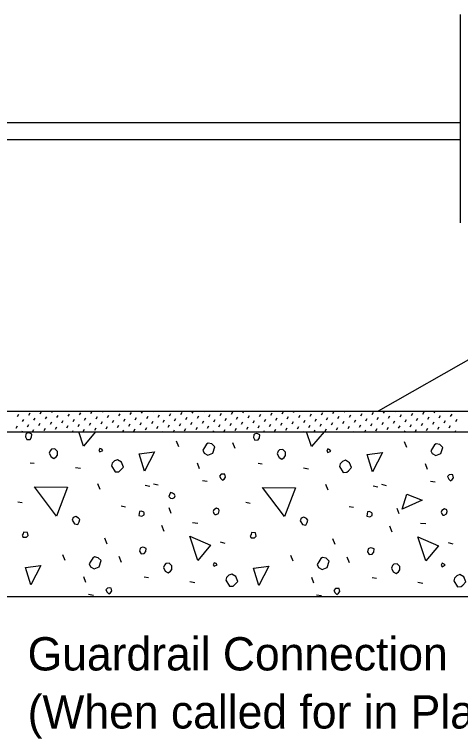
# Model space of a CAD drawing. Extents: x 130649.2 to 130733.9, y 88659.3 to 88705.5.
# Drawn here: x 130683.854 to 130686.559, y 88685.896 to 88690.285 of the extents above; entities that cross this region are included whole.
import ezdxf

# ---------------------------------------------------------------- set-up
doc = ezdxf.new("R2010")
doc.units = 0
for name, color, linetype in [('AdhocPoint_dp', 7, 'Continuous'), ('PlotBorder_dp', 7, 'Continuous'), ('TextMisc', 7, 'Continuous')]:
    doc.layers.add(name, color=color, linetype=linetype)

msp = doc.modelspace()

# ---------------------------------------------------------------- linework, layer by layer
at = {"layer": 'AdhocPoint_dp'}
for p, q in [((130673.2282, 88689.6313), (130686.5589, 88689.6313)), ((130689.0589, 88689.5896), (130686.0591, 88687.8812)), ((130673.2282, 88689.5271), (130686.5589, 88689.5271)), ((130673.2282, 88687.8812), (130689.0593, 88687.8812)), ((130673.2282, 88687.7562), (130689.0593, 88687.7562)), ((130673.2282, 88686.7562), (130689.0593, 88686.7562))]:
    msp.add_line(p, q, dxfattribs=at)
at = {"layer": 'TextMisc'}
for p, q in [((130686.559, 88689.0229), (130686.5589, 88690.2852)), ((130683.942, 88687.8556), (130683.9501, 88687.8696)), ((130684.0112, 88687.8637), (130684.0193, 88687.8777)), ((130684.0804, 88687.8718), (130684.0858, 88687.8812)), ((130684.1495, 88687.8799), (130684.1503, 88687.8812)), ((130684.2492, 88687.8575), (130684.2573, 88687.8715)), ((130684.3184, 88687.8656), (130684.3265, 88687.8796)), ((130684.3876, 88687.8737), (130684.3919, 88687.8812)), ((130684.4873, 88687.8513), (130684.4954, 88687.8653)), ((130684.5564, 88687.8594), (130684.5645, 88687.8734)), ((130684.6256, 88687.8675), (130684.6335, 88687.8812)), ((130684.6947, 88687.8756), (130684.698, 88687.8812)), ((130684.7944, 88687.8532), (130684.8025, 88687.8672)), ((130684.8636, 88687.8613), (130684.8717, 88687.8753)), ((130684.9328, 88687.8694), (130684.9396, 88687.8812)), ((130685.0019, 88687.8775), (130685.0041, 88687.8812)), ((130685.1016, 88687.8551), (130685.1097, 88687.869)), ((130685.1708, 88687.8632), (130685.1789, 88687.8771)), ((130685.24, 88687.8713), (130685.2457, 88687.8812)), ((130685.3091, 88687.8794), (130685.3102, 88687.8812)), ((130685.4088, 88687.8569), (130685.4169, 88687.8709)), ((130685.478, 88687.865), (130685.4861, 88687.879)), ((130685.5471, 88687.8731), (130685.5518, 88687.8812)), ((130685.6468, 88687.8507), (130685.6549, 88687.8647)), ((130685.716, 88687.8588), (130685.7241, 88687.8728)), ((130685.7852, 88687.8669), (130685.7933, 88687.8809)), ((130685.8543, 88687.875), (130685.8579, 88687.8812)), ((130685.954, 88687.8526), (130685.9621, 88687.8666)), ((130686.0232, 88687.8607), (130686.0313, 88687.8747)), ((130686.0923, 88687.8688), (130686.0995, 88687.8812)), ((130686.1615, 88687.8769), (130686.164, 88687.8812)), ((130686.2612, 88687.8545), (130686.2693, 88687.8685)), ((130686.3304, 88687.8626), (130686.3385, 88687.8766)), ((130686.3995, 88687.8707), (130686.4056, 88687.8812)), ((130686.4687, 88687.8788), (130686.4701, 88687.8812)), ((130683.8729, 88687.8475), (130683.881, 88687.8615)), ((130683.9034, 88687.817), (130683.9115, 88687.831)), ((130683.9726, 88687.8251), (130683.9807, 88687.8391)), ((130684.0417, 88687.8332), (130684.0498, 88687.8472)), ((130684.1109, 88687.8413), (130684.119, 88687.8553)), ((130684.1414, 88687.8108), (130684.1495, 88687.8248)), ((130684.1801, 88687.8494), (130684.1882, 88687.8634)), ((130684.2106, 88687.8189), (130684.2187, 88687.8329)), ((130684.2798, 88687.827), (130684.2879, 88687.841)), ((130684.3489, 88687.8351), (130684.357, 88687.8491)), ((130684.4181, 88687.8432), (130684.4262, 88687.8572)), ((130684.4486, 88687.8127), (130684.4567, 88687.8267)), ((130684.5178, 88687.8208), (130684.5259, 88687.8348)), ((130684.5869, 88687.8289), (130684.5951, 88687.8429)), ((130684.6561, 88687.837), (130684.6642, 88687.851)), ((130684.6866, 88687.8064), (130684.6947, 88687.8204)), ((130684.7253, 88687.8451), (130684.7334, 88687.8591)), ((130684.7558, 88687.8145), (130684.7639, 88687.8285)), ((130684.825, 88687.8226), (130684.8331, 88687.8366)), ((130684.8941, 88687.8307), (130684.9022, 88687.8447)), ((130684.9633, 88687.8388), (130684.9714, 88687.8528)), ((130684.9938, 88687.8083), (130685.0019, 88687.8223)), ((130685.0325, 88687.8469), (130685.0406, 88687.8609)), ((130685.063, 88687.8164), (130685.0711, 88687.8304)), ((130685.1322, 88687.8245), (130685.1403, 88687.8385)), ((130685.2013, 88687.8326), (130685.2094, 88687.8466)), ((130685.2705, 88687.8407), (130685.2786, 88687.8547)), ((130685.301, 88687.8102), (130685.3091, 88687.8242)), ((130685.3396, 88687.8488), (130685.3478, 88687.8628)), ((130685.3702, 88687.8183), (130685.3783, 88687.8323)), ((130685.4393, 88687.8264), (130685.4474, 88687.8404)), ((130685.5085, 88687.8345), (130685.5166, 88687.8485)), ((130685.5777, 88687.8426), (130685.5858, 88687.8566)), ((130685.6082, 88687.8121), (130685.6163, 88687.8261)), ((130685.6774, 88687.8202), (130685.6855, 88687.8342)), ((130685.7465, 88687.8283), (130685.7546, 88687.8423)), ((130685.8157, 88687.8364), (130685.8238, 88687.8504)), ((130685.8849, 88687.8445), (130685.893, 88687.8585)), ((130685.9154, 88687.814), (130685.9235, 88687.8279)), ((130685.9846, 88687.8221), (130685.9927, 88687.836)), ((130686.0537, 88687.8302), (130686.0618, 88687.8442)), ((130686.1229, 88687.8383), (130686.131, 88687.8523)), ((130686.1534, 88687.8077), (130686.1615, 88687.8217)), ((130686.192, 88687.8464), (130686.2001, 88687.8604)), ((130686.2226, 88687.8158), (130686.2307, 88687.8298)), ((130686.2917, 88687.8239), (130686.2998, 88687.8379)), ((130686.3609, 88687.832), (130686.369, 88687.846)), ((130686.4301, 88687.8401), (130686.4382, 88687.8541)), ((130686.4606, 88687.8096), (130686.4687, 88687.8236)), ((130686.4992, 88687.8482), (130686.5073, 88687.8622)), ((130686.5298, 88687.8177), (130686.5379, 88687.8317)), ((130683.8648, 88687.7784), (130683.8729, 88687.7924)), ((130683.9339, 88687.7865), (130683.942, 88687.8005)), ((130684.0031, 88687.7946), (130684.0112, 88687.8086)), ((130684.0336, 88687.764), (130684.0417, 88687.778)), ((130684.0723, 88687.8027), (130684.0804, 88687.8167)), ((130684.1028, 88687.7722), (130684.1109, 88687.7861)), ((130684.172, 88687.7803), (130684.1801, 88687.7942)), ((130684.2411, 88687.7884), (130684.2492, 88687.8024)), ((130684.3103, 88687.7965), (130684.3184, 88687.8105)), ((130684.3408, 88687.7659), (130684.3489, 88687.7799)), ((130684.3795, 88687.8046), (130684.3876, 88687.8186)), ((130684.41, 88687.774), (130684.4181, 88687.788)), ((130684.4792, 88687.7821), (130684.4873, 88687.7961)), ((130684.5483, 88687.7902), (130684.5564, 88687.8042)), ((130684.6175, 88687.7983), (130684.6256, 88687.8123)), ((130684.648, 88687.7678), (130684.6561, 88687.7818)), ((130684.7172, 88687.7759), (130684.7253, 88687.7899)), ((130684.7863, 88687.784), (130684.7944, 88687.798)), ((130684.8555, 88687.7921), (130684.8636, 88687.8061)), ((130684.9247, 88687.8002), (130684.9328, 88687.8142)), ((130684.9552, 88687.7697), (130684.9633, 88687.7837)), ((130685.0244, 88687.7778), (130685.0325, 88687.7918)), ((130685.0935, 88687.7859), (130685.1016, 88687.7999)), ((130685.1627, 88687.794), (130685.1708, 88687.808)), ((130685.1932, 88687.7635), (130685.2013, 88687.7775)), ((130685.2319, 88687.8021), (130685.24, 88687.8161)), ((130685.2624, 88687.7716), (130685.2705, 88687.7856)), ((130685.3315, 88687.7797), (130685.3396, 88687.7937)), ((130685.4007, 88687.7878), (130685.4088, 88687.8018)), ((130685.4699, 88687.7959), (130685.478, 88687.8099)), ((130685.5004, 88687.7653), (130685.5085, 88687.7793)), ((130685.539, 88687.804), (130685.5471, 88687.818)), ((130685.5696, 88687.7734), (130685.5777, 88687.7874)), ((130685.6387, 88687.7815), (130685.6468, 88687.7955)), ((130685.7079, 88687.7896), (130685.716, 88687.8036)), ((130685.7771, 88687.7977), (130685.7852, 88687.8117)), ((130685.8076, 88687.7672), (130685.8157, 88687.7812)), ((130685.8462, 88687.8058), (130685.8543, 88687.8198)), ((130685.8768, 88687.7753), (130685.8849, 88687.7893)), ((130685.9459, 88687.7834), (130685.954, 88687.7974)), ((130686.0151, 88687.7915), (130686.0232, 88687.8055)), ((130686.0842, 88687.7996), (130686.0923, 88687.8136)), ((130686.1148, 88687.7691), (130686.1229, 88687.7831)), ((130686.1839, 88687.7772), (130686.192, 88687.7912)), ((130686.2531, 88687.7853), (130686.2612, 88687.7993)), ((130686.3223, 88687.7934), (130686.3304, 88687.8074)), ((130686.3528, 88687.7629), (130686.3609, 88687.7769)), ((130686.3914, 88687.8015), (130686.3995, 88687.8155)), ((130686.422, 88687.771), (130686.4301, 88687.785)), ((130686.4911, 88687.7791), (130686.4992, 88687.7931)), ((130683.9002, 88687.7562), (130683.9034, 88687.7618)), ((130683.9646, 88687.7562), (130683.9726, 88687.7699)), ((130684.2063, 88687.7562), (130684.2106, 88687.7637)), ((130684.2717, 88687.7578), (130684.2798, 88687.7718)), ((130684.4479, 88687.7562), (130684.4486, 88687.7575)), ((130684.5124, 88687.7562), (130684.5178, 88687.7656)), ((130684.5788, 88687.7597), (130684.5869, 88687.7737)), ((130684.754, 88687.7562), (130684.7558, 88687.7594)), ((130684.8185, 88687.7562), (130684.825, 88687.7675)), ((130684.886, 88687.7616), (130684.8941, 88687.7756)), ((130685.0601, 88687.7562), (130685.063, 88687.7612)), ((130685.1246, 88687.7562), (130685.1322, 88687.7694)), ((130685.3662, 88687.7562), (130685.3702, 88687.7631)), ((130685.4312, 88687.7572), (130685.4393, 88687.7712)), ((130685.6078, 88687.7562), (130685.6082, 88687.7569)), ((130685.6723, 88687.7562), (130685.6774, 88687.765)), ((130685.7384, 88687.7591), (130685.7465, 88687.7731)), ((130685.9139, 88687.7562), (130685.9154, 88687.7588)), ((130685.9784, 88687.7562), (130685.9846, 88687.7669)), ((130686.0456, 88687.761), (130686.0537, 88687.775)), ((130686.22, 88687.7562), (130686.2226, 88687.7607)), ((130686.2845, 88687.7562), (130686.2917, 88687.7688)), ((130686.5261, 88687.7562), (130686.5298, 88687.7625)), ((130684.8504, 88687.6639), (130684.8362, 88687.6992)), ((130685.1933, 88687.6533), (130685.1792, 88687.6886)), ((130686.2328, 88687.6603), (130686.2186, 88687.6957)), ((130683.9488, 88687.5684), (130683.9736, 88687.5649)), ((130684.9759, 88687.5313), (130684.9635, 88687.5649)), ((130685.3312, 88687.5649), (130685.356, 88687.5614)), ((130686.3583, 88687.5278), (130686.3459, 88687.5614)), ((130684.2246, 88687.5401), (130684.2546, 88687.5348)), ((130685.607, 88687.5366), (130685.637, 88687.5313)), ((130684.3731, 88687.4058), (130684.3607, 88687.4394)), ((130684.6471, 88687.4323), (130684.6754, 88687.4252)), ((130684.6983, 88687.4411), (130684.7266, 88687.4341)), ((130684.9936, 88687.4606), (130685.0236, 88687.4553)), ((130685.7555, 88687.4023), (130685.7431, 88687.4358)), ((130686.0295, 88687.4288), (130686.0578, 88687.4217)), ((130686.0807, 88687.4376), (130686.109, 88687.4305)), ((130686.376, 88687.4571), (130686.406, 88687.4518)), ((130683.8746, 88687.3315), (130683.9011, 88687.3262)), ((130684.5004, 88687.3068), (130684.5269, 88687.3015)), ((130684.8044, 88687.2608), (130684.792, 88687.2944)), ((130685.257, 88687.328), (130685.2835, 88687.3227)), ((130685.8828, 88687.3033), (130685.9093, 88687.298)), ((130686.1868, 88687.2573), (130686.1744, 88687.2909)), ((130684.9335, 88687.206), (130684.9653, 88687.2025)), ((130684.762, 88687.1512), (130684.7478, 88687.1866)), ((130686.1444, 88687.1477), (130686.1302, 88687.1831)), ((130686.3159, 88687.2025), (130686.3477, 88687.199)), ((130684.4173, 88687.0752), (130684.4031, 88687.1106)), ((130685.1014, 88687.0876), (130685.1297, 88687.0805)), ((130685.7997, 88687.0717), (130685.7855, 88687.107)), ((130686.4838, 88687.0841), (130686.5121, 88687.077)), ((130684.1609, 88686.9745), (130684.1468, 88687.0098)), ((130684.5039, 88686.9638), (130684.4898, 88686.9992)), ((130685.5433, 88686.9709), (130685.5292, 88687.0063)), ((130685.8863, 88686.9603), (130685.8721, 88686.9957)), ((130684.2865, 88686.8419), (130684.2741, 88686.8755)), ((130684.6418, 88686.8755), (130684.6665, 88686.8719)), ((130685.6689, 88686.8383), (130685.6565, 88686.8719)), ((130686.0242, 88686.8719), (130686.0489, 88686.8684)), ((130684.9176, 88686.8472), (130684.9476, 88686.8419)), ((130686.2999, 88686.8436), (130686.33, 88686.8383)), ((130684.3041, 88686.7712), (130684.3342, 88686.7659)), ((130685.6865, 88686.7676), (130685.7166, 88686.7623))]:
    msp.add_line(p, q, dxfattribs=at)
for points in [[(130683.9205, 88687.724), (130683.9294, 88687.7081), (130683.9488, 88687.7098), (130683.9577, 88687.7222), (130683.9594, 88687.7417), (130683.947, 88687.747), (130683.9382, 88687.7487), (130683.9276, 88687.7452), (130683.9241, 88687.7417), (130683.9205, 88687.724)], [(130684.2723, 88687.6692), (130684.244, 88687.7562)], [(130684.346, 88687.7562), (130684.2723, 88687.6692)], [(130685.3029, 88687.7205), (130685.3118, 88687.7045), (130685.3312, 88687.7063), (130685.34, 88687.7187), (130685.3418, 88687.7381), (130685.3294, 88687.7434), (130685.3206, 88687.7452), (130685.31, 88687.7417), (130685.3065, 88687.7381), (130685.3029, 88687.7205)], [(130685.6547, 88687.6657), (130685.6253, 88687.7562)], [(130685.7313, 88687.7562), (130685.6547, 88687.6657)], [(130684.0655, 88687.625), (130684.0761, 88687.6038), (130684.0938, 88687.5932), (130684.1079, 88687.6038), (130684.115, 88687.6144), (130684.115, 88687.6356), (130684.0991, 88687.6515), (130684.0796, 88687.6497), (130684.0708, 88687.6409), (130684.0655, 88687.625)], [(130684.3713, 88687.6338), (130684.3908, 88687.6427), (130684.3837, 88687.6497), (130684.3713, 88687.655), (130684.366, 88687.6427), (130684.3713, 88687.6338)], [(130685.0042, 88687.6268), (130685.0272, 88687.6144), (130685.0572, 88687.6268), (130685.0696, 88687.6639), (130685.0519, 88687.6816), (130685.0289, 88687.6869), (130685.0183, 88687.6798), (130685.0059, 88687.6603), (130684.9971, 88687.6444), (130685.0042, 88687.6268)], [(130685.4479, 88687.6215), (130685.4585, 88687.6002), (130685.4762, 88687.5896), (130685.4903, 88687.6002), (130685.4974, 88687.6109), (130685.4974, 88687.6321), (130685.4815, 88687.648), (130685.462, 88687.6462), (130685.4532, 88687.6374), (130685.4479, 88687.6215)], [(130685.7537, 88687.6303), (130685.7732, 88687.6391), (130685.7661, 88687.6462), (130685.7537, 88687.6515), (130685.7484, 88687.6391), (130685.7537, 88687.6303)], [(130686.3866, 88687.6232), (130686.4095, 88687.6109), (130686.4396, 88687.6232), (130686.452, 88687.6603), (130686.4343, 88687.678), (130686.4113, 88687.6833), (130686.4007, 88687.6763), (130686.3883, 88687.6568), (130686.3795, 88687.6409), (130686.3866, 88687.6232)], [(130684.6435, 88687.5172), (130684.61, 88687.6215), (130684.7037, 88687.6338), (130684.6435, 88687.5172)], [(130686.0259, 88687.5136), (130685.9924, 88687.6179), (130686.086, 88687.6303), (130686.0259, 88687.5136)], [(130684.442, 88687.549), (130684.465, 88687.5119), (130684.488, 88687.5136), (130684.4968, 88687.5225), (130684.5163, 88687.5419), (130684.5039, 88687.572), (130684.4791, 88687.5861), (130684.4615, 88687.579), (130684.4473, 88687.5649), (130684.442, 88687.549)], [(130685.8244, 88687.5454), (130685.8474, 88687.5083), (130685.8704, 88687.5101), (130685.8792, 88687.5189), (130685.8987, 88687.5384), (130685.8863, 88687.5684), (130685.8615, 88687.5826), (130685.8439, 88687.5755), (130685.8297, 88687.5614), (130685.8244, 88687.5454)], [(130685.1049, 88687.473), (130685.1155, 88687.4624), (130685.1261, 88687.4694), (130685.1332, 88687.48), (130685.1297, 88687.4977), (130685.1208, 88687.4995), (130685.1085, 88687.4977), (130685.0979, 88687.4871), (130685.1049, 88687.473)], [(130686.4873, 88687.4694), (130686.4979, 88687.4588), (130686.5085, 88687.4659), (130686.5156, 88687.4765), (130686.5121, 88687.4942), (130686.5032, 88687.4959), (130686.4909, 88687.4942), (130686.4803, 88687.4836), (130686.4873, 88687.4694)], [(130684.1097, 88687.2449), (130683.9753, 88687.4217), (130684.1751, 88687.4199), (130684.1097, 88687.2449)], [(130684.8009, 88687.3528), (130684.8133, 88687.351), (130684.8256, 88687.3563), (130684.8292, 88687.3669), (130684.8239, 88687.3757), (130684.8133, 88687.3828), (130684.8009, 88687.3881), (130684.7938, 88687.374), (130684.7903, 88687.3634), (130684.8009, 88687.3528)], [(130685.4921, 88687.2414), (130685.3577, 88687.4182), (130685.5575, 88687.4164), (130685.4921, 88687.2414)], [(130686.2045, 88687.2856), (130686.2328, 88687.3775), (130686.3265, 88687.3404), (130686.2045, 88687.2856)], [(130684.6082, 88687.2485), (130684.6276, 88687.2432), (130684.64, 88687.252), (130684.6418, 88687.2644), (130684.6382, 88687.2679), (130684.6241, 88687.275), (130684.6117, 88687.2732), (130684.61, 88687.2608), (130684.6082, 88687.2485)], [(130685.0696, 88687.2538), (130685.0767, 88687.2538), (130685.0908, 88687.2608), (130685.0961, 88687.2767), (130685.0943, 88687.2856), (130685.0802, 88687.2927), (130685.0625, 88687.282), (130685.059, 88687.2714), (130685.0625, 88687.2608), (130685.0696, 88687.2538)], [(130685.9906, 88687.2449), (130686.01, 88687.2396), (130686.0224, 88687.2485), (130686.0242, 88687.2608), (130686.0206, 88687.2644), (130686.0065, 88687.2714), (130685.9941, 88687.2697), (130685.9924, 88687.2573), (130685.9906, 88687.2449)], [(130686.452, 88687.2502), (130686.459, 88687.2502), (130686.4732, 88687.2573), (130686.4785, 88687.2732), (130686.4767, 88687.282), (130686.4626, 88687.2891), (130686.4449, 88687.2785), (130686.4414, 88687.2679), (130686.4449, 88687.2573), (130686.452, 88687.2502)], [(130684.2087, 88687.2131), (130684.2175, 88687.1972), (130684.2387, 88687.1937), (130684.2476, 88687.2096), (130684.2511, 88687.2237), (130684.2423, 88687.2325), (130684.2264, 88687.2414), (130684.2104, 88687.2361), (130684.2051, 88687.2202), (130684.2087, 88687.2131)], [(130685.5911, 88687.2096), (130685.5999, 88687.1937), (130685.6211, 88687.1901), (130685.63, 88687.206), (130685.6335, 88687.2202), (130685.6247, 88687.229), (130685.6087, 88687.2379), (130685.5928, 88687.2325), (130685.5875, 88687.2166), (130685.5911, 88687.2096)], [(130683.9064, 88687.1159), (130683.9276, 88687.1159), (130683.9382, 88687.1265), (130683.9329, 88687.1459), (130683.9099, 88687.1477), (130683.9064, 88687.1371), (130683.9011, 88687.1283), (130683.9064, 88687.1159), (130683.9029, 88687.1194)], [(130684.9653, 88686.9762), (130684.9176, 88687.1229), (130685.0431, 88687.0681), (130684.9653, 88686.9762)], [(130685.2888, 88687.1123), (130685.31, 88687.1123), (130685.3206, 88687.1229), (130685.3153, 88687.1424), (130685.2923, 88687.1442), (130685.2888, 88687.1336), (130685.2835, 88687.1247), (130685.2888, 88687.1123), (130685.2852, 88687.1159)], [(130686.3477, 88686.9727), (130686.2999, 88687.1194), (130686.4255, 88687.0646), (130686.3477, 88686.9727)], [(130684.6135, 88687.031), (130684.6223, 88687.0151), (130684.6418, 88687.0169), (130684.6506, 88687.0293), (130684.6524, 88687.0487), (130684.64, 88687.054), (130684.6312, 88687.0558), (130684.6206, 88687.0522), (130684.617, 88687.0487), (130684.6135, 88687.031)], [(130685.9959, 88687.0275), (130686.0047, 88687.0116), (130686.0242, 88687.0133), (130686.033, 88687.0257), (130686.0348, 88687.0452), (130686.0224, 88687.0505), (130686.0136, 88687.0522), (130686.003, 88687.0487), (130685.9994, 88687.0452), (130685.9959, 88687.0275)], [(130684.3147, 88686.9373), (130684.3377, 88686.925), (130684.3678, 88686.9373), (130684.3802, 88686.9745), (130684.3625, 88686.9921), (130684.3395, 88686.9974), (130684.3289, 88686.9904), (130684.3165, 88686.9709), (130684.3077, 88686.955), (130684.3147, 88686.9373)], [(130685.6971, 88686.9338), (130685.7201, 88686.9214), (130685.7502, 88686.9338), (130685.7625, 88686.9709), (130685.7449, 88686.9886), (130685.7219, 88686.9939), (130685.7113, 88686.9868), (130685.6989, 88686.9674), (130685.6901, 88686.9515), (130685.6971, 88686.9338)], [(130683.9541, 88686.8277), (130683.9205, 88686.932), (130684.0142, 88686.9444), (130683.9541, 88686.8277)], [(130684.7585, 88686.932), (130684.7691, 88686.9108), (130684.7867, 88686.9002), (130684.8009, 88686.9108), (130684.808, 88686.9214), (130684.808, 88686.9426), (130684.792, 88686.9585), (130684.7726, 88686.9568), (130684.7638, 88686.9479), (130684.7585, 88686.932)], [(130685.0643, 88686.9409), (130685.0837, 88686.9497), (130685.0767, 88686.9568), (130685.0643, 88686.9621), (130685.059, 88686.9497), (130685.0643, 88686.9409)], [(130686.1408, 88686.9285), (130686.1515, 88686.9073), (130686.1691, 88686.8967), (130686.1833, 88686.9073), (130686.1903, 88686.9179), (130686.1903, 88686.9391), (130686.1744, 88686.955), (130686.155, 88686.9532), (130686.1462, 88686.9444), (130686.1408, 88686.9285)], [(130686.4467, 88686.9373), (130686.4661, 88686.9462), (130686.459, 88686.9532), (130686.4467, 88686.9585), (130686.4414, 88686.9462), (130686.4467, 88686.9373)], [(130685.3365, 88686.8242), (130685.3029, 88686.9285), (130685.3966, 88686.9409), (130685.3365, 88686.8242)], [(130685.135, 88686.856), (130685.158, 88686.8189), (130685.1809, 88686.8207), (130685.1898, 88686.8295), (130685.2092, 88686.8489), (130685.1969, 88686.879), (130685.1721, 88686.8931), (130685.1544, 88686.8861), (130685.1403, 88686.8719), (130685.135, 88686.856)], [(130686.5174, 88686.8525), (130686.5404, 88686.8154), (130686.5633, 88686.8171), (130686.5722, 88686.826), (130686.5916, 88686.8454), (130686.5793, 88686.8755), (130686.5545, 88686.8896), (130686.5368, 88686.8825), (130686.5227, 88686.8684), (130686.5174, 88686.8525)], [(130684.4155, 88686.7835), (130684.4261, 88686.7729), (130684.4367, 88686.78), (130684.4438, 88686.7906), (130684.4403, 88686.8083), (130684.4314, 88686.8101), (130684.419, 88686.8083), (130684.4084, 88686.7977), (130684.4155, 88686.7835)], [(130685.7979, 88686.78), (130685.8085, 88686.7694), (130685.8191, 88686.7765), (130685.8262, 88686.7871), (130685.8226, 88686.8047), (130685.8138, 88686.8065), (130685.8014, 88686.8047), (130685.7908, 88686.7941), (130685.7979, 88686.78)]]:
    msp.add_lwpolyline(points, dxfattribs=at)

# ---------------------------------------------------------------- texts
at = {"layer": 'PlotBorder_dp'}
for s, p in [('Guardrail Connection', (130683.9342, 88686.3089)), ('(When called for in Plans)', (130683.9342, 88685.9569))]:
    msp.add_text(s, height=0.2016, dxfattribs=at).set_placement(p)

doc.saveas('drawing.dxf')
